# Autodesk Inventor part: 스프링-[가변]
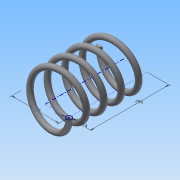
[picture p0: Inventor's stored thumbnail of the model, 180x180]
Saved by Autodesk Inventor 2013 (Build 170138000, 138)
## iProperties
Created: 2015-03
Part Number: 스프링-[가변]
Material: 강철, 탄소
Document SubType Name: Modeling
Designer: Administrator
Density: 7.87 g/cm^3
Mass: 48.2733 g
Surface Area: 62.0009 cm^2
Volume: 6.13384 cm^3
Author: Administrator
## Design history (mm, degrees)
sketch "스케치1"
  geometry: L1 (0, 0)-(17.5, 0); L2 (17.5, 0)-(17.5, 43.5); L3 (17.5, 43.5)-(0, 43.5); L4 (0, 43.5)-(0, 0); C1 r 2 at (17.5, 0)
  constraints: 8 end point, 2 parallel, 1 centre point, 1 coincident, 1 horizontal, 1 perpendicular
  dimensions: "d0" = 4 diameter of C1; "d2" = 35 diameter of L2 L4; "d3" = 43.5 distance between parallel lines of L3 L1 (derived)
feature "코일1" sketch "스케치1" pitch "d4" = 10; turns "d6" = 4.5; dims "d5" = 43.5 (= d3), "d7" = 0, angle "d8" = 90 deg, angle "d9" = 90 deg, "d10" = 0, "d11" = 0
sketch "스케치2"
  geometry: L1 (-19.5, 0)-(-15.5, 0) reference; L2 (-19.5, 0)-(-15.5, 0) reference; 1 further point
  constraints: 2 horizontal alignment
extrude "돌출1" cut sketch "스케치2" distance "d12" = 10; taper "d13" = 0 deg
node "작업 평면1"
sketch "스케치3"
  geometry: L1 (-19.5, 0)-(-15.5, 0) reference; 1 further point
  constraints: 1 horizontal alignment
extrude "돌출2" cut sketch "스케치3" distance "d15" = 10; taper "d16" = 0 deg
node "솔리드1"
node "절단 모서리 투영1"
node "절단 모서리 투영2"
node "절단 모서리 투영3"
other parameters: "d14" = -43.5 (= -d3)
